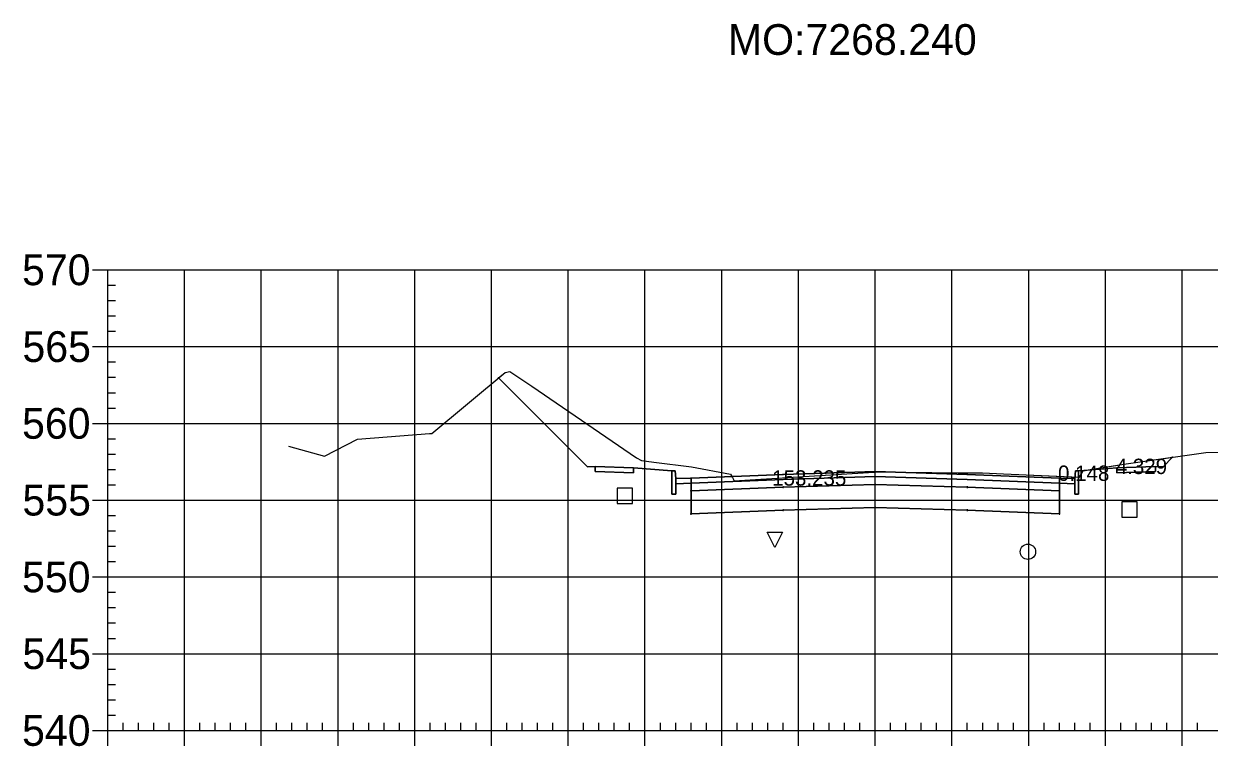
# Model space of a CAD drawing. Extents: x 704834 to 709892, y 372981 to 377533.
# Drawn here: x 706850.9 to 707005.4, y 373850.8 to 373944.9 of the extents above; entities that cross this region are included whole.
import ezdxf

# ---------------------------------------------------------------- set-up
doc = ezdxf.new("R2010")
doc.units = 0
for name, color, linetype in [('1', 7, 'Continuous'), ('10', 7, 'Continuous'), ('13', 7, 'Continuous'), ('14', 7, 'Continuous'), ('4', 7, 'Continuous'), ('57', 7, 'Continuous'), ('59', 7, 'Continuous'), ('Default_Xsect', 7, 'Continuous'), ('Existing', 7, 'Continuous')]:
    doc.layers.add(name, color=color, linetype=linetype)

msp = doc.modelspace()

# ---------------------------------------------------------------- linework, layer by layer
for points in [[(706924.37, 373887.18), (706912.8, 373898.75)], [(706925.37, 373887.22), (706924.37, 373887.18)], [(706998.37, 373887.22), (706999.37, 373887.18)], [(706999.37, 373887.18), (707000.59, 373888.4)], [(706935.37, 373886.62), (706930.37, 373887.02)], [(706988.37, 373886.62), (706993.37, 373887.02)]]:
    msp.add_lwpolyline(points)
for points in [[(706930.37, 373887.02), (706925.37, 373887.22), (706925.37, 373886.56), (706930.37, 373886.36)], [(706993.37, 373886.36), (706998.37, 373886.56), (706998.37, 373887.22), (706993.37, 373887.02)], [(706935.87, 373885.62), (706935.79, 373886.62), (706935.37, 373886.62), (706935.37, 373883.62), (706935.87, 373883.62)], [(706937.87, 373885.7), (706935.87, 373885.62), (706935.87, 373884.96), (706937.87, 373885.04)], [(706961.87, 373885.88), (706973.87, 373885.52), (706985.87, 373885.04), (706985.87, 373885.7), (706973.87, 373886.18), (706961.87, 373886.54), (706949.87, 373886.18), (706937.87, 373885.7), (706937.87, 373885.04), (706949.87, 373885.52)], [(706961.87, 373884.88), (706973.87, 373884.52), (706985.87, 373884.04), (706985.87, 373885.04), (706973.87, 373885.52), (706961.87, 373885.88), (706949.87, 373885.52), (706937.87, 373885.04), (706937.87, 373884.04), (706949.87, 373884.52)], [(706961.82, 373885.83), (706961.92, 373885.83), (706961.92, 373885.93), (706961.82, 373885.93)], [(706985.87, 373885.04), (706987.87, 373884.96), (706987.87, 373885.62), (706985.87, 373885.7)], [(706987.87, 373883.62), (706988.37, 373883.62), (706988.37, 373886.62), (706987.96, 373886.62), (706987.87, 373885.62)], [(706961.87, 373881.88), (706973.87, 373881.52), (706985.87, 373881.04), (706985.87, 373884.04), (706973.87, 373884.52), (706961.87, 373884.88), (706949.87, 373884.52), (706937.87, 373884.04), (706937.87, 373881.04), (706949.87, 373881.52)], [(706949.82, 373884.47), (706949.92, 373884.47), (706949.92, 373884.57), (706949.82, 373884.57)], [(706961.82, 373884.83), (706961.92, 373884.83), (706961.92, 373884.93), (706961.82, 373884.93)], [(706973.82, 373884.47), (706973.92, 373884.47), (706973.92, 373884.57), (706973.82, 373884.57)], [(706937.82, 373883.99), (706937.92, 373883.99), (706937.92, 373884.09), (706937.82, 373884.09)], [(706985.82, 373883.99), (706985.92, 373883.99), (706985.92, 373884.09), (706985.82, 373884.09)], [(706937.82, 373880.99), (706937.92, 373880.99), (706937.92, 373881.09), (706937.82, 373881.09)], [(706949.82, 373881.47), (706949.92, 373881.47), (706949.92, 373881.57), (706949.82, 373881.57)], [(706961.82, 373881.83), (706961.92, 373881.83), (706961.92, 373881.93), (706961.82, 373881.93)], [(706973.82, 373881.47), (706973.92, 373881.47), (706973.92, 373881.57), (706973.82, 373881.57)], [(706985.82, 373880.99), (706985.92, 373880.99), (706985.92, 373881.09), (706985.82, 373881.09)]]:
    msp.add_lwpolyline(points, close=True)
at = {"layer": '1'}
for points in [[(706912.8, 373898.75), (706913.66, 373899.46), (706914.24, 373899.59), (706914.77, 373899.23), (706917.12, 373897.65), (706930.78, 373888.35), (706931.4, 373888), (706933.04, 373887.77), (706937.92, 373887.16), (706943, 373886.21), (706943.26, 373885.78), (706943.51, 373885.33), (706958.15, 373886.27), (706962.41, 373886.53), (706972.69, 373886.38), (706975.83, 373886.37), (706978.57, 373886.24), (706988.37, 373885.82), (706988.37, 373883.62), (706987.87, 373883.62), (706987.87, 373884.96), (706985.87, 373885.04), (706985.87, 373884.04), (706985.87, 373881.04), (706973.87, 373881.52), (706961.87, 373881.88), (706949.87, 373881.52), (706937.87, 373881.04), (706937.87, 373884.04), (706937.87, 373885.04), (706935.87, 373884.96), (706935.87, 373883.62), (706935.37, 373883.62), (706935.37, 373886.62), (706930.37, 373887.02), (706930.37, 373886.36), (706925.37, 373886.56), (706925.37, 373887.22), (706924.37, 373887.18)], [(706989.07, 373886.68), (706994.26, 373887.5), (707000.59, 373888.4), (706999.37, 373887.18), (706998.37, 373887.22), (706998.37, 373886.56), (706993.37, 373886.36), (706993.37, 373887.02), (706991, 373886.83), (706991, 373886.83), (706990.99, 373886.83), (706990.98, 373886.83), (706990.97, 373886.83)], [(706988.37, 373885.82), (706988.49, 373885.81), (706988.92, 373886.55), (706988.98, 373886.66), (706989.07, 373886.68), (706988.37, 373886.62)], [(706948.78, 373876.67), (706947.78, 373878.67), (706949.78, 373878.67)]]:
    msp.add_lwpolyline(points, close=True, dxfattribs=at)
at = {"layer": '10'}
msp.add_lwpolyline([(706928.26, 373882.38), (706930.26, 373882.38), (706930.26, 373884.38), (706928.26, 373884.38)], close=True, dxfattribs=at)
at = {"layer": '13'}
msp.add_circle((706981.77, 373876.1), 1, dxfattribs=at)
at = {"layer": '14'}
for points in [[(706912.8, 373898.75), (706912.8, 373898.8), (706912.8, 373898.75), (706912.75, 373898.75), (706912.8, 373898.75), (706912.8, 373898.7), (706912.8, 373898.75), (706912.85, 373898.75)], [(707000.59, 373888.4), (707000.59, 373888.45), (707000.59, 373888.4), (707000.54, 373888.4), (707000.59, 373888.4), (707000.59, 373888.35), (707000.59, 373888.4), (707000.64, 373888.4)], [(706937.87, 373885.7), (706937.87, 373885.75), (706937.87, 373885.7), (706937.82, 373885.7), (706937.87, 373885.7), (706937.87, 373885.65), (706937.87, 373885.7), (706937.92, 373885.7)], [(706949.87, 373886.18), (706949.87, 373886.23), (706949.87, 373886.18), (706949.82, 373886.18), (706949.87, 373886.18), (706949.87, 373886.13), (706949.87, 373886.18), (706949.92, 373886.18)], [(706961.87, 373886.54), (706961.87, 373886.59), (706961.87, 373886.54), (706961.82, 373886.54), (706961.87, 373886.54), (706961.87, 373886.49), (706961.87, 373886.54), (706961.92, 373886.54)], [(706973.87, 373886.18), (706973.87, 373886.23), (706973.87, 373886.18), (706973.82, 373886.18), (706973.87, 373886.18), (706973.87, 373886.13), (706973.87, 373886.18), (706973.92, 373886.18)], [(706985.87, 373885.7), (706985.87, 373885.75), (706985.87, 373885.7), (706985.82, 373885.7), (706985.87, 373885.7), (706985.87, 373885.65), (706985.87, 373885.7), (706985.92, 373885.7)]]:
    msp.add_lwpolyline(points, dxfattribs=at)
at = {"layer": '4'}
msp.add_lwpolyline([(706994.02, 373880.61), (706996.02, 373880.61), (706996.02, 373882.61), (706994.02, 373882.61)], close=True, dxfattribs=at)
at = {"layer": '57'}
for p, q in [((706859.87, 373912.82), (706861.87, 373912.82)), ((706861.87, 373912.82), (707061.87, 373912.82)), ((706861.87, 373852.82), (706861.87, 373912.82)), ((706861.87, 373852.82), (706861.87, 373912.82)), ((706871.87, 373852.82), (706871.87, 373912.82)), ((706881.87, 373852.82), (706881.87, 373912.82)), ((706891.87, 373852.82), (706891.87, 373912.82)), ((706901.87, 373852.82), (706901.87, 373912.82)), ((706911.87, 373852.82), (706911.87, 373912.82)), ((706921.87, 373852.82), (706921.87, 373912.82)), ((706931.87, 373852.82), (706931.87, 373912.82)), ((706941.87, 373852.82), (706941.87, 373912.82)), ((706951.87, 373852.82), (706951.87, 373912.82)), ((706961.87, 373852.82), (706961.87, 373912.82)), ((706971.87, 373852.82), (706971.87, 373912.82)), ((706981.87, 373852.82), (706981.87, 373912.82)), ((706991.87, 373852.82), (706991.87, 373912.82)), ((707001.87, 373852.82), (707001.87, 373912.82)), ((706861.87, 373910.82), (706862.87, 373910.82)), ((706861.87, 373908.82), (706862.87, 373908.82)), ((706861.87, 373906.82), (706862.87, 373906.82)), ((706861.87, 373904.82), (706862.87, 373904.82)), ((706859.87, 373902.82), (706861.87, 373902.82)), ((706861.87, 373902.82), (707061.87, 373902.82)), ((706861.87, 373900.82), (706862.87, 373900.82)), ((706861.87, 373898.82), (706862.87, 373898.82)), ((706861.87, 373896.82), (706862.87, 373896.82)), ((706861.87, 373894.82), (706862.87, 373894.82)), ((706859.87, 373892.82), (706861.87, 373892.82)), ((706861.87, 373892.82), (707061.87, 373892.82)), ((706861.87, 373890.82), (706862.87, 373890.82)), ((706861.87, 373888.82), (706862.87, 373888.82)), ((706861.87, 373886.82), (706862.87, 373886.82)), ((706861.87, 373884.82), (706862.87, 373884.82)), ((706859.87, 373882.82), (706861.87, 373882.82)), ((706861.87, 373882.82), (707061.87, 373882.82)), ((706861.87, 373880.82), (706862.87, 373880.82)), ((706861.87, 373878.82), (706862.87, 373878.82)), ((706861.87, 373876.82), (706862.87, 373876.82)), ((706861.87, 373874.82), (706862.87, 373874.82)), ((706859.87, 373872.82), (706861.87, 373872.82)), ((706861.87, 373872.82), (707061.87, 373872.82)), ((706861.87, 373870.82), (706862.87, 373870.82)), ((706861.87, 373868.82), (706862.87, 373868.82)), ((706861.87, 373866.82), (706862.87, 373866.82)), ((706861.87, 373864.82), (706862.87, 373864.82)), ((706859.87, 373862.82), (706861.87, 373862.82)), ((706861.87, 373862.82), (707061.87, 373862.82)), ((706861.87, 373860.82), (706862.87, 373860.82)), ((706861.87, 373858.82), (706862.87, 373858.82)), ((706861.87, 373856.82), (706862.87, 373856.82)), ((706861.87, 373854.82), (706862.87, 373854.82)), ((706863.87, 373852.82), (706863.87, 373853.82)), ((706865.87, 373852.82), (706865.87, 373853.82)), ((706867.87, 373852.82), (706867.87, 373853.82)), ((706869.87, 373852.82), (706869.87, 373853.82)), ((706873.87, 373852.82), (706873.87, 373853.82)), ((706875.87, 373852.82), (706875.87, 373853.82)), ((706877.87, 373852.82), (706877.87, 373853.82)), ((706879.87, 373852.82), (706879.87, 373853.82)), ((706883.87, 373852.82), (706883.87, 373853.82)), ((706885.87, 373852.82), (706885.87, 373853.82)), ((706887.87, 373852.82), (706887.87, 373853.82)), ((706889.87, 373852.82), (706889.87, 373853.82)), ((706893.87, 373852.82), (706893.87, 373853.82)), ((706895.87, 373852.82), (706895.87, 373853.82)), ((706897.87, 373852.82), (706897.87, 373853.82)), ((706899.87, 373852.82), (706899.87, 373853.82)), ((706903.87, 373852.82), (706903.87, 373853.82)), ((706905.87, 373852.82), (706905.87, 373853.82)), ((706907.87, 373852.82), (706907.87, 373853.82)), ((706909.87, 373852.82), (706909.87, 373853.82)), ((706913.87, 373852.82), (706913.87, 373853.82)), ((706915.87, 373852.82), (706915.87, 373853.82)), ((706917.87, 373852.82), (706917.87, 373853.82)), ((706919.87, 373852.82), (706919.87, 373853.82)), ((706923.87, 373852.82), (706923.87, 373853.82)), ((706925.87, 373852.82), (706925.87, 373853.82)), ((706927.87, 373852.82), (706927.87, 373853.82)), ((706929.87, 373852.82), (706929.87, 373853.82)), ((706933.87, 373852.82), (706933.87, 373853.82)), ((706935.87, 373852.82), (706935.87, 373853.82)), ((706937.87, 373852.82), (706937.87, 373853.82)), ((706939.87, 373852.82), (706939.87, 373853.82)), ((706943.87, 373852.82), (706943.87, 373853.82)), ((706945.87, 373852.82), (706945.87, 373853.82)), ((706947.87, 373852.82), (706947.87, 373853.82)), ((706949.87, 373852.82), (706949.87, 373853.82)), ((706953.87, 373852.82), (706953.87, 373853.82)), ((706955.87, 373852.82), (706955.87, 373853.82)), ((706957.87, 373852.82), (706957.87, 373853.82)), ((706959.87, 373852.82), (706959.87, 373853.82)), ((706963.87, 373852.82), (706963.87, 373853.82)), ((706965.87, 373852.82), (706965.87, 373853.82)), ((706967.87, 373852.82), (706967.87, 373853.82)), ((706969.87, 373852.82), (706969.87, 373853.82)), ((706973.87, 373852.82), (706973.87, 373853.82)), ((706975.87, 373852.82), (706975.87, 373853.82)), ((706977.87, 373852.82), (706977.87, 373853.82)), ((706979.87, 373852.82), (706979.87, 373853.82)), ((706983.87, 373852.82), (706983.87, 373853.82)), ((706985.87, 373852.82), (706985.87, 373853.82)), ((706987.87, 373852.82), (706987.87, 373853.82)), ((706989.87, 373852.82), (706989.87, 373853.82)), ((706993.87, 373852.82), (706993.87, 373853.82)), ((706995.87, 373852.82), (706995.87, 373853.82)), ((706997.87, 373852.82), (706997.87, 373853.82)), ((706999.87, 373852.82), (706999.87, 373853.82)), ((707003.87, 373852.82), (707003.87, 373853.82)), ((706859.87, 373852.82), (706861.87, 373852.82)), ((706861.87, 373852.82), (707061.87, 373852.82)), ((706861.87, 373852.82), (707061.87, 373852.82)), ((706861.87, 373850.82), (706861.87, 373852.82)), ((706871.87, 373850.82), (706871.87, 373852.82)), ((706881.87, 373850.82), (706881.87, 373852.82)), ((706891.87, 373850.82), (706891.87, 373852.82)), ((706901.87, 373850.82), (706901.87, 373852.82)), ((706911.87, 373850.82), (706911.87, 373852.82)), ((706921.87, 373850.82), (706921.87, 373852.82)), ((706931.87, 373850.82), (706931.87, 373852.82)), ((706941.87, 373850.82), (706941.87, 373852.82)), ((706951.87, 373850.82), (706951.87, 373852.82)), ((706961.87, 373850.82), (706961.87, 373852.82)), ((706971.87, 373850.82), (706971.87, 373852.82)), ((706981.87, 373850.82), (706981.87, 373852.82)), ((706991.87, 373850.82), (706991.87, 373852.82)), ((707001.87, 373850.82), (707001.87, 373852.82))]:
    msp.add_line(p, q, dxfattribs=at)
at = {"layer": 'Default_Xsect'}
msp.add_lwpolyline([(706912.8, 373898.75), (706924.37, 373887.18), (706925.37, 373887.22), (706930.37, 373887.02), (706935.37, 373886.62), (706935.79, 373886.62), (706935.87, 373885.62), (706937.87, 373885.7), (706949.87, 373886.18), (706961.87, 373886.54), (706973.87, 373886.18), (706985.87, 373885.7), (706987.87, 373885.62), (706987.96, 373886.62), (706988.37, 373886.62), (706993.37, 373887.02), (706998.37, 373887.22), (706999.37, 373887.18), (707000.59, 373888.4)], dxfattribs=at)
at = {"layer": 'Existing'}
msp.add_lwpolyline([(706885.41, 373889.87), (706890.1, 373888.54), (706894.41, 373890.75), (706903.79, 373891.51), (706904.09, 373891.5), (706913.66, 373899.46), (706914.24, 373899.59), (706914.77, 373899.23), (706917.12, 373897.65), (706930.78, 373888.35), (706931.4, 373888), (706933.04, 373887.77), (706937.92, 373887.16), (706943, 373886.21), (706943.26, 373885.78), (706943.51, 373885.33), (706958.15, 373886.27), (706962.41, 373886.53), (706972.69, 373886.38), (706975.83, 373886.37), (706978.57, 373886.24), (706988.49, 373885.81), (706988.92, 373886.55), (706988.98, 373886.66), (706994.26, 373887.5), (707004.93, 373889.02), (707011.17, 373889.13)], dxfattribs=at)

# ---------------------------------------------------------------- texts
at = {"layer": '14'}
for p in [(706925.34, 373887.17), (706998.34, 373887.17), (706925.34, 373886.51), (706930.34, 373886.31), (706993.34, 373886.31), (706998.34, 373886.51)]:
    msp.add_text('+', height=0.1, dxfattribs=at).set_placement(p)
at = {"layer": '57'}
for s, p in [('570', (706850.7, 373910.82)), ('565', (706850.75, 373900.82)), ('560', (706850.7, 373890.82)), ('555', (706850.75, 373880.82)), ('550', (706850.7, 373870.82)), ('545', (706850.75, 373860.82)), ('540', (706850.7, 373850.82))]:
    msp.add_text(s, height=4, dxfattribs=at).set_placement(p)
at = {"layer": '59'}
for s, height, p in [('MO:7268.240', 4, (706942.68, 373940.82)), ('0.148', 2, (706985.69, 373885.33)), ('4.329', 2, (706993.21, 373886.22)), ('153.235', 2, (706948.44, 373884.71))]:
    msp.add_text(s, height=height, dxfattribs=at).set_placement(p)

doc.saveas('drawing.dxf')
